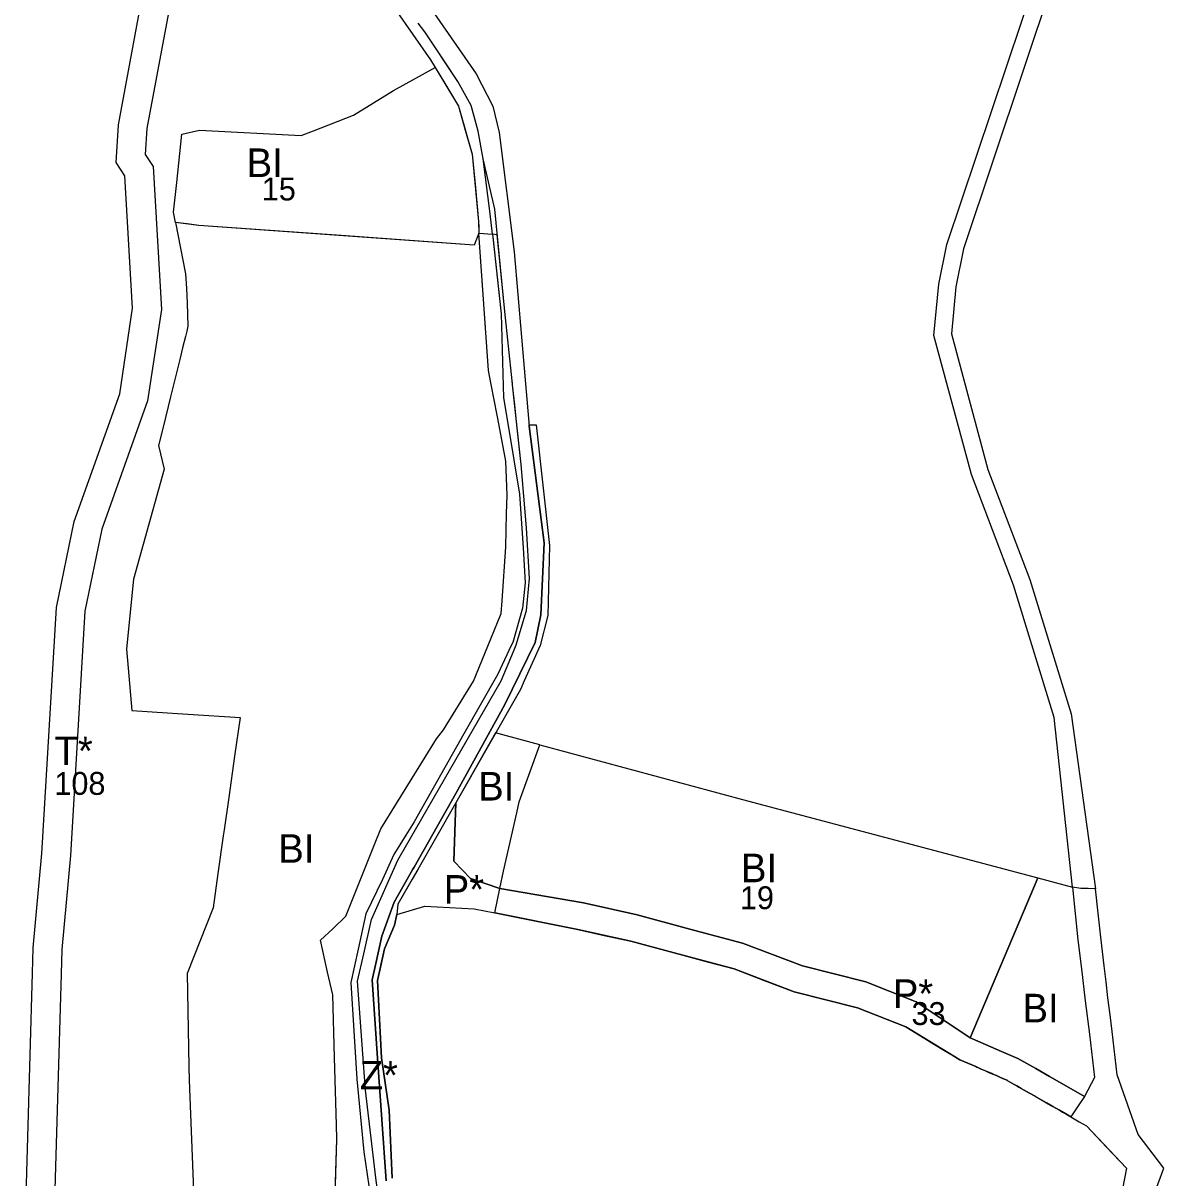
# Model space of a CAD drawing. Extents: x -521621 to -516769, y -1190068 to -1185078.
# Drawn here: x -519013.9 to -518615, y -1186753.4 to -1186349.3 of the extents above; entities that cross this region are included whole.
import ezdxf

# ---------------------------------------------------------------- set-up
doc = ezdxf.new("R2010")
doc.units = 0
for name, color, linetype in [('bydleni_n', 7, 'Continuous'), ('bydleni_s', 7, 'Continuous'), ('fpl_id', 7, 'Continuous'), ('s_zelen_s', 7, 'Continuous'), ('v_infrastr_n', 7, 'Continuous'), ('v_infrastr_s', 7, 'Continuous'), ('voda_s', 7, 'Continuous')]:
    doc.layers.add(name, color=color, linetype=linetype)

msp = doc.modelspace()

# ---------------------------------------------------------------- linework, layer by layer
at = {"layer": 'bydleni_n'}
for points in [[(-518960.22, -1186405.05), (-518958.38, -1186388.14), (-518952.31, -1186386.77), (-518916.75, -1186388.69), (-518912.4, -1186387), (-518898.44, -1186381.57), (-518884.36, -1186372.97), (-518869.84, -1186364.89), (-518861.7, -1186378.35), (-518856.87, -1186395.23), (-518854.66, -1186418.7), (-518854.51, -1186422.83), (-518856.22, -1186426.98), (-518952.47, -1186420.17), (-518960.66, -1186419.04), (-518961.36, -1186415.48)], [(-518840.42, -1186621.85), (-518833.21, -1186601.86), (-518760.61, -1186621.4), (-518659.09, -1186648.39), (-518660.25, -1186651.13), (-518682.77, -1186704.33), (-518701.66, -1186691.76), (-518719.19, -1186684.77), (-518741.41, -1186679.19), (-518762.31, -1186671.22), (-518780.73, -1186666.29), (-518799.19, -1186661.36), (-518817.92, -1186657.17), (-518847.25, -1186652.06), (-518845.98, -1186646.05), (-518842.23, -1186629.74), (-518841.28, -1186625.59)]]:
    msp.add_lwpolyline(points, close=True, dxfattribs=at)
at = {"layer": 'bydleni_s'}
for p, q in [((-518962.39, -1186480.13), (-518964.98, -1186490.67)), ((-518964.98, -1186490.67), (-518966.56, -1186497.09)), ((-518966.56, -1186497.09), (-518964.65, -1186505.44)), ((-518844.7, -1186514.48), (-518845.11, -1186502.56)), ((-518964.65, -1186505.44), (-518971.96, -1186531.76)), ((-518844.84, -1186520.91), (-518844.7, -1186514.48)), ((-518845.11, -1186532.55), (-518844.84, -1186520.91)), ((-518846.38, -1186551.48), (-518845.11, -1186532.55)), ((-518856.4, -1186579.63), (-518850.32, -1186564.75)), ((-518904.91, -1186763.85), (-518904.18, -1186739.87))]:
    msp.add_line(p, q, dxfattribs=at)
for points in [[(-518855.37, -1186424.91), (-518856.22, -1186426.98), (-518904.35, -1186423.57), (-518952.47, -1186420.17), (-518956.57, -1186419.6), (-518960.66, -1186419.04), (-518958.89, -1186428.07), (-518957.11, -1186437.11), (-518956.84, -1186442.18), (-518956.57, -1186447.25), (-518956.43, -1186451.28), (-518956.29, -1186455.32), (-518956.74, -1186457.16), (-518957.19, -1186459), (-518958.17, -1186463), (-518959.16, -1186467), (-518959.61, -1186468.85), (-518960.07, -1186470.71)], [(-518847.47, -1186490.16), (-518848.18, -1186486.45), (-518850.2, -1186475.81), (-518851.13, -1186470.93), (-518854.51, -1186422.83), (-518855.37, -1186424.91)], [(-518960.07, -1186470.71), (-518962.39, -1186480.13)], [(-518845.11, -1186502.56), (-518847.47, -1186490.16)], [(-518971.96, -1186531.76), (-518975.33, -1186543.91), (-518975.55, -1186546.15)], [(-518975.55, -1186546.15), (-518977.79, -1186568.42), (-518977.22, -1186574.99)], [(-518850.32, -1186564.75), (-518846.72, -1186555.86), (-518846.38, -1186551.48)], [(-518977.22, -1186574.99), (-518975.93, -1186589.78), (-518956.28, -1186591.07), (-518938.04, -1186592.28)], [(-518866.94, -1186596.57), (-518856.4, -1186579.63)], [(-518938.04, -1186592.28), (-518939.97, -1186605.84), (-518942.02, -1186620.28)], [(-518883.34, -1186622.34), (-518869.42, -1186599.79), (-518866.94, -1186596.57)], [(-518844.83, -1186598.73), (-518848.67, -1186597.7), (-518862.55, -1186622.16), (-518863.25, -1186642.59), (-518857.5, -1186648.65), (-518847.25, -1186652.06)], [(-518841.28, -1186625.59), (-518840.42, -1186621.85), (-518833.21, -1186601.86), (-518844.83, -1186598.73)], [(-518942.02, -1186620.28), (-518943.63, -1186631.56), (-518943.92, -1186633.64)], [(-518891.05, -1186636.74), (-518888.86, -1186631.29), (-518883.34, -1186622.34)], [(-518845.98, -1186646.05), (-518842.23, -1186629.74), (-518841.28, -1186625.59)], [(-518943.92, -1186633.64), (-518945.8, -1186646.81)], [(-518896.23, -1186649.6), (-518891.05, -1186636.74)], [(-518945.8, -1186646.81), (-518947.51, -1186658.86)], [(-518847.25, -1186652.06), (-518845.98, -1186646.05)], [(-518660.25, -1186651.13), (-518659.09, -1186648.39), (-518646.98, -1186651.61), (-518645.02, -1186670.08)], [(-518905.59, -1186666.18), (-518901.12, -1186661.75), (-518896.23, -1186649.6)], [(-518896.23, -1186649.6), (-518896.23, -1186649.6)], [(-518677.4, -1186706.65), (-518682.77, -1186704.33), (-518660.25, -1186651.13)], [(-518947.51, -1186658.86), (-518956.56, -1186681.85)], [(-518884.9, -1186753.45), (-518885.91, -1186729.7), (-518888.61, -1186711.35), (-518890.04, -1186684.31), (-518887.51, -1186673.2), (-518884.06, -1186664.95), (-518883.22, -1186661.24), (-518873.45, -1186658.29), (-518856.19, -1186659.22), (-518849.01, -1186660.65), (-518838.04, -1186662.84), (-518834.45, -1186663.56), (-518819.89, -1186666.46), (-518810.67, -1186668.53), (-518801.45, -1186670.59), (-518792.32, -1186673.03), (-518783.18, -1186675.47), (-518774.21, -1186677.87), (-518765.24, -1186680.27), (-518754.76, -1186684.27), (-518744.27, -1186688.27), (-518733.2, -1186691.05), (-518722.12, -1186693.83), (-518705.25, -1186700.55), (-518698.6, -1186704.6), (-518695.81, -1186706.29), (-518691.95, -1186708.64), (-518689.16, -1186710.34), (-518686.37, -1186712.03), (-518684.97, -1186712.64), (-518683.57, -1186713.24), (-518682.17, -1186713.85), (-518680.77, -1186714.45), (-518680.41, -1186714.61), (-518680.05, -1186714.77), (-518678.82, -1186715.3), (-518677.59, -1186715.83), (-518676.17, -1186716.44), (-518674.75, -1186717.05), (-518673.53, -1186717.58), (-518672.32, -1186718.11), (-518671.07, -1186718.65), (-518669.82, -1186719.2), (-518669.75, -1186719.24), (-518667.29, -1186720.65), (-518666.38, -1186721.17), (-518665.65, -1186721.59), (-518664.83, -1186722.06), (-518664.02, -1186722.52), (-518662.02, -1186723.67), (-518660.03, -1186724.81), (-518658.04, -1186725.95), (-518656.04, -1186727.1), (-518653.78, -1186728.39), (-518651.52, -1186729.69), (-518650.4, -1186730.34), (-518649.27, -1186730.98), (-518647.52, -1186731.99), (-518644.54, -1186733.73), (-518642.07, -1186735.17), (-518635.04, -1186742.57), (-518628.01, -1186749.96), (-518629.41, -1186757.16)], [(-518907.44, -1186681.41), (-518909.99, -1186670.2), (-518905.59, -1186666.18)], [(-518645.02, -1186670.08), (-518643.8, -1186680.17)], [(-518905.03, -1186711.2), (-518905.64, -1186689.3), (-518907.44, -1186681.41)], [(-518643.8, -1186680.17), (-518642.45, -1186691.37)], [(-518956.56, -1186681.85), (-518955.93, -1186714.39), (-518955.84, -1186719.13)], [(-518642.45, -1186691.37), (-518641.03, -1186703.1)], [(-518641.03, -1186703.1), (-518639.2, -1186718.23)], [(-518671.75, -1186709.09), (-518677.4, -1186706.65)], [(-518666.07, -1186711.55), (-518671.75, -1186709.09)], [(-518904.18, -1186739.87), (-518904.37, -1186734.83), (-518905.03, -1186711.2)], [(-518659.79, -1186715.15), (-518666.07, -1186711.55)], [(-518655.02, -1186717.88), (-518659.79, -1186715.15)], [(-518649.07, -1186721.3), (-518655.02, -1186717.88)], [(-518955.84, -1186719.13), (-518954.36, -1186757.76), (-518954.01, -1186767.14)], [(-518639.2, -1186718.23), (-518642.77, -1186724.91), (-518649.07, -1186721.3)]]:
    msp.add_lwpolyline(points, dxfattribs=at)
at = {"layer": 's_zelen_s'}
for points in [[(-518848.1, -1186423.36), (-518849.8, -1186423.22)], [(-518849.8, -1186423.22), (-518846.74, -1186451.05), (-518845.89, -1186480.45), (-518844.31, -1186490.09)], [(-518845.47, -1186450.21), (-518848.1, -1186423.36)], [(-518844.17, -1186462.32), (-518845.47, -1186450.21)], [(-518842.8, -1186475.15), (-518842.88, -1186474.44), (-518844.17, -1186462.32)], [(-518842.73, -1186475.85), (-518842.8, -1186475.15)], [(-518841.97, -1186482.94), (-518842.73, -1186475.85)], [(-518841.21, -1186490.03), (-518841.97, -1186482.94)], [(-518886.92, -1186754.41), (-518889.95, -1186711.48), (-518891.84, -1186684.04), (-518890.59, -1186678.39), (-518888.47, -1186668.81), (-518884.15, -1186656.88), (-518877.59, -1186645.33), (-518877.2, -1186644.64), (-518862.58, -1186618.86), (-518845.6, -1186587.92), (-518834.81, -1186566.08), (-518832.93, -1186556.38), (-518831.71, -1186531.17), (-518836.97, -1186490.39), (-518837.01, -1186489.94), (-518834.56, -1186489.89), (-518829.85, -1186532.08), (-518830.47, -1186556.54), (-518833.11, -1186567.1), (-518838.67, -1186579.45), (-518840.03, -1186582.48), (-518862.55, -1186622.16), (-518875.9, -1186645.45), (-518882.88, -1186657.62), (-518883.22, -1186661.24), (-518884.06, -1186664.95), (-518887.51, -1186673.2), (-518889, -1186679.68), (-518890.04, -1186684.31), (-518888.61, -1186711.35), (-518885.91, -1186729.7), (-518884.9, -1186753.45)], [(-518844.31, -1186490.09), (-518840.38, -1186514.09)], [(-518842.49, -1186569.14), (-518841.54, -1186566.83), (-518837.83, -1186554.84), (-518836.87, -1186543.7), (-518837.83, -1186525.87), (-518839.74, -1186503.8), (-518841.21, -1186490.03)], [(-518840.38, -1186514.09), (-518839.1, -1186532.88), (-518838.36, -1186545.19), (-518839.32, -1186553.99), (-518842.71, -1186566.09), (-518843.2, -1186567.12)], [(-518843.2, -1186567.12), (-518847.91, -1186577.13), (-518859.8, -1186598.03), (-518877.19, -1186628.77), (-518880.09, -1186633.48), (-518884.33, -1186640.2), (-518888.24, -1186649.02), (-518894.07, -1186660.97), (-518896.76, -1186673.37), (-518899.27, -1186684.95), (-518897.26, -1186718.8), (-518894.82, -1186744.27), (-518891.85, -1186764.12), (-518888.34, -1186776.32), (-518885.16, -1186782.48), (-518873.11, -1186802.87), (-518872.45, -1186803.99), (-518870.19, -1186807.8), (-518868.29, -1186811.02), (-518865.1, -1186819.73), (-518861.03, -1186834.46)], [(-518859.27, -1186833.63), (-518864.25, -1186815.37), (-518867.86, -1186806.99), (-518868.43, -1186805.99), (-518870.76, -1186801.91), (-518871.43, -1186800.73), (-518871.68, -1186800.3), (-518881.62, -1186784.32), (-518885.69, -1186775.58), (-518889.3, -1186763.06), (-518890.57, -1186753.29), (-518894.18, -1186722.73), (-518897.05, -1186684.52), (-518894.83, -1186674.94), (-518892.06, -1186662.98), (-518882.83, -1186642.18), (-518882.39, -1186641.41), (-518846.74, -1186579.46), (-518842.49, -1186569.14)]]:
    msp.add_lwpolyline(points, dxfattribs=at)
at = {"layer": 'v_infrastr_n'}
for points in [[(-518653.75, -1186334.83), (-518685.06, -1186428.31), (-518687.78, -1186441.61), (-518689.3, -1186458.1), (-518676.58, -1186505.47), (-518661.89, -1186543.99), (-518647.39, -1186591.03), (-518638.87, -1186652.2), (-518643.96, -1186652.12), (-518646.98, -1186651.61), (-518653.29, -1186592.24), (-518667.57, -1186545.95), (-518682.3, -1186507.32), (-518695.37, -1186458.62), (-518693.72, -1186440.73), (-518690.87, -1186426.75), (-518659.45, -1186332.96)], [(-519013.95, -1186796.5), (-519010.62, -1186681.73), (-519010.37, -1186672.85), (-519007.34, -1186639.83), (-519002.24, -1186553.84), (-518996.08, -1186523.69), (-518980.14, -1186479.03), (-518975.64, -1186449.11), (-518978.31, -1186402.75), (-518981.4, -1186398.1), (-518980.61, -1186384.96), (-518972.97, -1186343.95)], [(-518963.14, -1186345.78), (-518970.67, -1186386.18), (-518971.22, -1186395.35), (-518968.48, -1186399.46), (-518965.6, -1186449.57), (-518970.4, -1186481.48), (-518986.42, -1186526.39), (-518992.3, -1186555.14), (-518997.37, -1186640.58), (-519000.38, -1186673.45), (-519000.63, -1186681.98), (-519003.96, -1186797.13)], [(-518849.01, -1186660.65), (-518847.25, -1186652.06)], [(-518847.25, -1186652.06), (-518817.92, -1186657.17), (-518799.19, -1186661.36), (-518780.73, -1186666.29), (-518762.31, -1186671.22), (-518741.41, -1186679.19), (-518719.19, -1186684.77), (-518701.66, -1186691.76), (-518682.77, -1186704.33)], [(-518819.89, -1186666.46), (-518849.01, -1186660.65)], [(-518801.45, -1186670.59), (-518819.89, -1186666.46)], [(-518783.18, -1186675.47), (-518801.45, -1186670.59)], [(-518765.24, -1186680.27), (-518783.18, -1186675.47)], [(-518744.27, -1186688.27), (-518765.24, -1186680.27)], [(-518722.12, -1186693.83), (-518744.27, -1186688.27)], [(-518705.25, -1186700.55), (-518722.12, -1186693.83)], [(-518686.37, -1186712.03), (-518705.25, -1186700.55)], [(-518682.77, -1186704.33), (-518677.4, -1186706.65)], [(-518677.4, -1186706.65), (-518671.75, -1186709.09)], [(-518671.75, -1186709.09), (-518666.07, -1186711.55)], [(-518680.77, -1186714.45), (-518686.37, -1186712.03)], [(-518666.07, -1186711.55), (-518659.79, -1186715.15)], [(-518678.82, -1186715.3), (-518680.05, -1186714.77), (-518680.77, -1186714.45)], [(-518674.75, -1186717.05), (-518675.12, -1186716.89), (-518678.82, -1186715.3)], [(-518673.53, -1186717.58), (-518674.75, -1186717.05)], [(-518672.32, -1186718.11), (-518673.53, -1186717.58)], [(-518659.79, -1186715.15), (-518655.02, -1186717.88)], [(-518655.02, -1186717.88), (-518649.07, -1186721.3)], [(-518669.82, -1186719.2), (-518671.07, -1186718.65), (-518672.32, -1186718.11)], [(-518667.29, -1186720.65), (-518669.75, -1186719.24), (-518669.82, -1186719.2)], [(-518666.38, -1186721.17), (-518667.29, -1186720.65)], [(-518664.02, -1186722.52), (-518664.83, -1186722.06), (-518666.38, -1186721.17)], [(-518649.07, -1186721.3), (-518642.77, -1186724.91)], [(-518662.02, -1186723.67), (-518664.02, -1186722.52)], [(-518660.03, -1186724.81), (-518662.02, -1186723.67)], [(-518659.77, -1186724.96), (-518660.03, -1186724.81)], [(-518656.04, -1186727.1), (-518659.77, -1186724.96)], [(-518642.77, -1186724.91), (-518645.14, -1186728.45)], [(-518653.78, -1186728.39), (-518656.04, -1186727.1)], [(-518651.52, -1186729.69), (-518653.78, -1186728.39)], [(-518649.27, -1186730.98), (-518651.52, -1186729.69)], [(-518645.14, -1186728.45), (-518647.52, -1186731.99), (-518649.27, -1186730.98)]]:
    msp.add_lwpolyline(points, dxfattribs=at)
at = {"layer": 'v_infrastr_s'}
for points in [[(-518883.82, -1186344.5), (-518871.5, -1186362.15), (-518869.84, -1186364.89)], [(-518866.46, -1186362.89), (-518873.44, -1186352.35), (-518875.78, -1186349.33)], [(-518869.84, -1186364.89), (-518866.6, -1186370.25), (-518861.7, -1186378.35), (-518859.29, -1186386.79), (-518856.87, -1186395.23), (-518855.77, -1186406.97), (-518854.66, -1186418.7), (-518854.59, -1186420.77)], [(-518849.8, -1186423.22), (-518850.59, -1186416.03), (-518853.04, -1186396.81), (-518854.84, -1186387.1), (-518857.24, -1186378.12), (-518861.88, -1186369.82), (-518866.46, -1186362.89)], [(-518854.59, -1186420.77), (-518854.51, -1186422.83)], [(-518854.51, -1186422.83), (-518849.8, -1186423.22)], [(-518854.28, -1186426.11), (-518854.51, -1186422.83), (-518849.8, -1186423.22)], [(-518847.47, -1186490.16), (-518848.18, -1186486.45), (-518850.2, -1186475.81), (-518851.13, -1186470.93), (-518854.28, -1186426.11)], [(-518849.8, -1186423.22), (-518849.71, -1186424.07)], [(-518849.71, -1186424.07), (-518846.74, -1186451.05), (-518845.89, -1186480.45), (-518844.31, -1186490.09)], [(-518904.91, -1186763.85), (-518904.18, -1186739.87), (-518904.37, -1186734.83), (-518905.03, -1186711.2), (-518905.64, -1186689.3), (-518907.44, -1186681.41), (-518909.99, -1186670.2), (-518905.59, -1186666.18), (-518901.12, -1186661.75), (-518901.12, -1186661.75), (-518896.23, -1186649.6), (-518891.05, -1186636.74), (-518891.05, -1186636.74), (-518888.86, -1186631.29), (-518883.34, -1186622.34), (-518883.34, -1186622.34), (-518869.42, -1186599.79), (-518866.94, -1186596.57), (-518856.4, -1186579.63), (-518856.4, -1186579.63), (-518850.32, -1186564.75), (-518846.72, -1186555.86), (-518846.38, -1186551.48), (-518845.11, -1186532.55), (-518844.84, -1186520.91), (-518844.7, -1186514.48), (-518845.11, -1186502.56), (-518847.47, -1186490.16)], [(-518844.31, -1186490.09), (-518840.38, -1186514.09), (-518839.1, -1186532.88), (-518838.36, -1186545.19), (-518839.32, -1186553.99), (-518842.71, -1186566.09), (-518843.2, -1186567.12), (-518847.91, -1186577.13), (-518859.8, -1186598.03), (-518877.19, -1186628.77), (-518880.09, -1186633.48), (-518884.33, -1186640.2), (-518888.24, -1186649.02), (-518894.07, -1186660.97), (-518896.76, -1186673.37), (-518899.27, -1186684.95), (-518897.26, -1186718.8), (-518894.82, -1186744.27), (-518891.85, -1186764.12)], [(-518849.01, -1186660.65), (-518847.25, -1186652.06), (-518857.5, -1186648.65), (-518863.25, -1186642.59), (-518862.55, -1186622.16), (-518875.9, -1186645.45), (-518877.83, -1186648.81)], [(-518877.83, -1186648.81), (-518882.88, -1186657.62), (-518883.22, -1186661.24), (-518873.45, -1186658.29)], [(-518632.48, -1186787.66), (-518618.97, -1186760.67), (-518614.96, -1186749.91), (-518623.97, -1186738.16), (-518631.26, -1186717.27), (-518633.09, -1186702.14), (-518633.8, -1186696.27), (-518634.51, -1186690.41), (-518635.18, -1186684.81), (-518635.86, -1186679.21), (-518636.46, -1186674.19), (-518637.07, -1186669.18), (-518637.97, -1186660.69), (-518638.87, -1186652.2), (-518641.42, -1186652.16), (-518643.96, -1186652.12), (-518646.98, -1186651.61), (-518645.02, -1186670.08), (-518643.8, -1186680.17), (-518642.45, -1186691.37), (-518641.03, -1186703.1), (-518639.2, -1186718.23), (-518642.77, -1186724.91), (-518645.14, -1186728.45)], [(-518873.45, -1186658.29), (-518856.19, -1186659.22), (-518849.01, -1186660.65)], [(-518645.14, -1186728.45), (-518647.52, -1186731.99), (-518644.54, -1186733.73), (-518642.07, -1186735.17), (-518628.01, -1186749.96), (-518629.41, -1186757.16), (-518644.11, -1186785.29)]]:
    msp.add_lwpolyline(points, dxfattribs=at)
at = {"layer": 'voda_s'}
for points in [[(-518879.84, -1186331.86), (-518855.44, -1186367.11)], [(-518848.98, -1186414.41), (-518853.04, -1186396.81), (-518854.84, -1186387.1), (-518857.24, -1186378.12), (-518861.88, -1186369.82), (-518873.44, -1186352.35), (-518875.78, -1186349.33)], [(-518855.44, -1186367.11), (-518849.64, -1186378.36)], [(-518849.64, -1186378.36), (-518847.49, -1186387.6)], [(-518847.49, -1186387.6), (-518842.16, -1186429.32)], [(-518845.47, -1186450.21), (-518848.98, -1186414.41)], [(-518842.16, -1186429.32), (-518838.35, -1186474.16)], [(-518842.88, -1186474.44), (-518845.47, -1186450.21)], [(-518842.73, -1186475.85), (-518842.88, -1186474.44)], [(-518838.35, -1186474.16), (-518838.23, -1186475.54)], [(-518838.23, -1186475.54), (-518836.97, -1186490.39)], [(-518839.74, -1186503.8), (-518842.73, -1186475.85)], [(-518836.97, -1186490.39), (-518831.71, -1186531.17)], [(-518837.83, -1186525.87), (-518839.74, -1186503.8)], [(-518836.87, -1186543.7), (-518837.83, -1186525.87)], [(-518831.71, -1186531.17), (-518832.93, -1186556.38)], [(-518837.83, -1186554.84), (-518836.87, -1186543.7)], [(-518841.54, -1186566.83), (-518837.83, -1186554.84)], [(-518832.93, -1186556.38), (-518834.81, -1186566.08)], [(-518834.81, -1186566.08), (-518845.6, -1186587.92)], [(-518842.49, -1186569.14), (-518841.54, -1186566.83)], [(-518846.74, -1186579.46), (-518842.49, -1186569.14)], [(-518882.39, -1186641.41), (-518846.74, -1186579.46)], [(-518845.6, -1186587.92), (-518862.58, -1186618.86)], [(-518862.58, -1186618.86), (-518877.2, -1186644.64)], [(-518892.06, -1186662.98), (-518882.83, -1186642.18)], [(-518882.83, -1186642.18), (-518882.39, -1186641.41)], [(-518877.2, -1186644.64), (-518877.59, -1186645.33)], [(-518877.59, -1186645.33), (-518884.15, -1186656.88)], [(-518884.15, -1186656.88), (-518888.47, -1186668.81)], [(-518894.83, -1186674.94), (-518892.06, -1186662.98)], [(-518888.47, -1186668.81), (-518890.59, -1186678.39)], [(-518897.05, -1186684.52), (-518894.83, -1186674.94)], [(-518890.59, -1186678.39), (-518891.84, -1186684.04)], [(-518894.18, -1186722.73), (-518897.05, -1186684.52)], [(-518891.84, -1186684.04), (-518889.95, -1186711.48)], [(-518889.95, -1186711.48), (-518886.92, -1186754.41)], [(-518890.57, -1186753.29), (-518894.18, -1186722.73)], [(-518889.3, -1186763.06), (-518890.57, -1186753.29)]]:
    msp.add_lwpolyline(points, dxfattribs=at)

# ---------------------------------------------------------------- texts
at = {"layer": 'bydleni_n'}
for p in [(-518935.75, -1186403.19), (-518762.88, -1186649.93)]:
    msp.add_text('BI', height=10, dxfattribs=at).set_placement(p)
at = {"layer": 'bydleni_s'}
for p in [(-518854.79, -1186621.34), (-518924.68, -1186643.12), (-518664.41, -1186698.96)]:
    msp.add_text('BI', height=10, dxfattribs=at).set_placement(p)
at = {"layer": 'fpl_id'}
for s, p in [('15', (-518930.46, -1186411.39)), ('108', (-519003, -1186619.35)), ('19', (-518763.24, -1186659.35)), ('33', (-518703.22, -1186699.87))]:
    msp.add_text(s, height=8, dxfattribs=at).set_placement(p)
at = {"layer": 's_zelen_s'}
msp.add_text('Z*', height=10, dxfattribs=at).set_placement((-518896.23, -1186722.42))
at = {"layer": 'v_infrastr_n'}
for s, p in [('T*', (-519002.95, -1186608.96)), ('P*', (-518709.77, -1186693.91))]:
    msp.add_text(s, height=10, dxfattribs=at).set_placement(p)
at = {"layer": 'v_infrastr_s'}
msp.add_text('P*', height=10, dxfattribs=at).set_placement((-518866.83, -1186657.43))

doc.saveas('drawing.dxf')
